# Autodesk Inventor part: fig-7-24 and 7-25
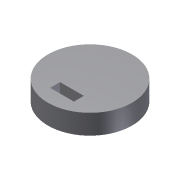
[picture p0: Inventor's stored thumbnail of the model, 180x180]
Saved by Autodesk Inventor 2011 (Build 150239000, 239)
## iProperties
Created: 2005-04
Part Number: fig-7-24 and 7-25
Document SubType Name: Modeling
Designer: CADCIM
Density: 1 g/cm^3
Author: CADCIM
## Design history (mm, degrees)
sketch "Sketch1"
  geometry: C1 r 21.205 at (0, 0)
  constraints: 1 centre point
extrude "Extrusion1" new body sketch "Sketch1" distance "d0" = 10; taper "d1" = 0 deg
sketch "Sketch2"
  geometry: L1 (-6, -9.113)-(6, -9.113); L2 (6, -9.113)-(6, -14.113); L3 (6, -14.113)-(-6, -14.113); L4 (-6, -14.113)-(-6, -9.113); C1 r 21.205 at (0, 0) reference
  constraints: 8 end point, 2 parallel, 1 horizontal, 1 perpendicular
  dimensions: "d2" = 6 distance from line of C1.centre L4; "d3" = 12 distance of L1.start L1.end; "d4" = 5 distance of L3.end L1.start
extrude "Extrusion2" cut sketch "Sketch2" stored distance "d5" = 10; taper "d6" = 0 deg
sketch "Sketch3"
  geometry: L1 (7.403, 8.063)-(-0.088, 16.951); L2 (-0.088, 16.951)-(-7.579, 8.063); A1 r 11.927 centre (-0.088, 17.344) between (-7.579, 8.063) and (7.403, 8.063)
  constraints: 4 end point, 2 point on circle, 1 centre point
extrude "Extrusion3" cut sketch "Sketch3" distance "d7" = 10; taper "d8" = 0 deg
body "Solid1"
